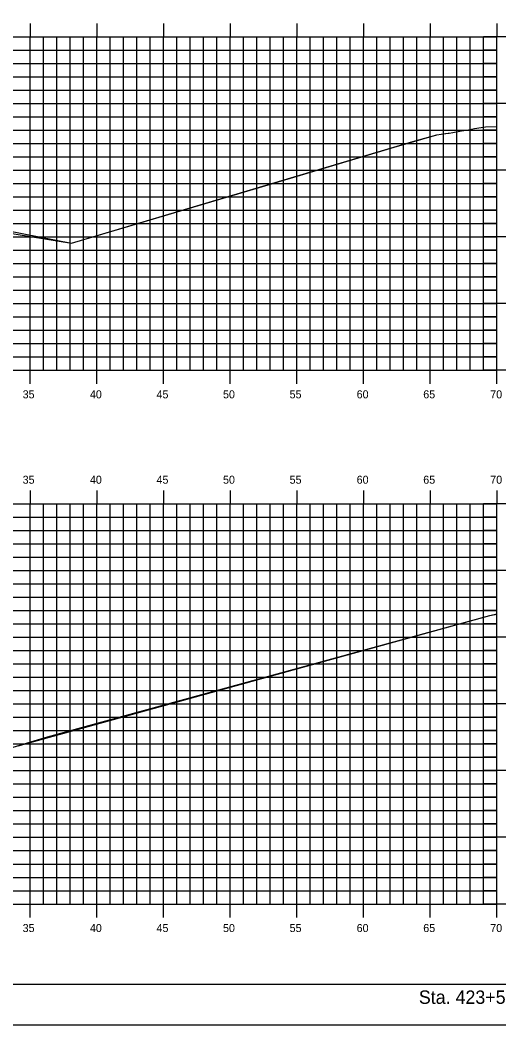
# Model space of a CAD drawing. Extents: x 1168600 to 1177589, y 610178 to 611246.
# Drawn here: x 1174776.1 to 1174812, y 610900.5 to 610975.8 of the extents above; entities that cross this region are included whole.
import ezdxf

# ---------------------------------------------------------------- set-up
doc = ezdxf.new("R2010")
doc.units = 0
for name, color, linetype in [('_Construction', 7, 'Continuous'), ('_Station Equation', 7, 'Continuous'), ('H_V ANNOTATION', 7, 'Continuous'), ('MAJOR', 7, 'Continuous'), ('MINOR', 7, 'Continuous')]:
    doc.layers.add(name, color=color, linetype=linetype)

msp = doc.modelspace()

# ---------------------------------------------------------------- linework, layer by layer
at = {"layer": '_Construction'}
msp.add_line((1174666.88, 610903.596), (1174826.88, 610903.596), dxfattribs=at)
msp.add_lwpolyline([(1174658.787, 610900.537), (1174828.787, 610900.537), (1174828.787, 611010.537), (1174658.787, 611010.537)], close=True, dxfattribs=at)
at = {"layer": '_Station Equation'}
for points in [[(1174689.898, 610959.391), (1174709.446, 610961.528), (1174724.212, 610962.049), (1174731.329, 610961.925), (1174745.178, 610961.326), (1174759.498, 610960.992), (1174772.679, 610960.549), (1174779.992, 610959.119), (1174805.578, 610966.736), (1174807.375, 610967.247), (1174808.025, 610967.336), (1174808.055, 610967.343), (1174808.217, 610967.367), (1174808.29, 610967.378), (1174808.572, 610967.421), (1174808.705, 610967.447), (1174808.852, 610967.478), (1174808.966, 610967.503), (1174809.234, 610967.549), (1174809.742, 610967.631), (1174810.19, 610967.708), (1174811.024, 610967.837), (1174811.88, 610967.868)], [(1174770.741, 610960.613), (1174779.992, 610959.119), (1174794.988, 610963.583), (1174804.189, 610966.323), (1174807.375, 610967.247), (1174808.025, 610967.336), (1174808.055, 610967.343), (1174808.216, 610967.367), (1174808.29, 610967.378), (1174808.572, 610967.421), (1174808.705, 610967.447), (1174808.852, 610967.478), (1174808.966, 610967.503), (1174809.234, 610967.549), (1174809.741, 610967.631), (1174810.19, 610967.708), (1174811.024, 610967.837), (1174811.88, 610967.868)], [(1174671.88, 610929.002), (1174688.235, 610920.975), (1174706.06, 610922.982), (1174712.304, 610920.417), (1174729.011, 610920.776), (1174736.819, 610920.456), (1174737.986, 610920.431), (1174765.818, 610919.558), (1174768.117, 610919.114), (1174778.192, 610922.119), (1174811.346, 610931.232), (1174811.88, 610931.325)], [(1174775.989, 610921.461), (1174811.346, 610931.232), (1174811.88, 610931.334)]]:
    msp.add_lwpolyline(points, dxfattribs=at)
at = {"layer": 'MAJOR'}
for p, q in [((1174776.88, 610975.598), (1174776.88, 610974.596)), ((1174781.88, 610975.598), (1174781.88, 610974.596)), ((1174786.88, 610975.598), (1174786.88, 610974.596)), ((1174791.88, 610975.598), (1174791.88, 610974.596)), ((1174796.88, 610975.598), (1174796.88, 610974.596)), ((1174801.88, 610975.598), (1174801.88, 610974.596)), ((1174806.88, 610975.598), (1174806.88, 610974.596)), ((1174811.88, 610975.598), (1174811.88, 610974.596)), ((1174671.88, 610974.596), (1174811.88, 610974.596)), ((1174671.88, 610974.596), (1174811.88, 610974.596)), ((1174776.88, 610949.596), (1174776.88, 610974.596)), ((1174781.88, 610949.596), (1174781.88, 610974.596)), ((1174786.88, 610949.596), (1174786.88, 610974.596)), ((1174791.88, 610949.596), (1174791.88, 610974.596)), ((1174796.88, 610949.596), (1174796.88, 610974.596)), ((1174801.88, 610949.596), (1174801.88, 610974.596)), ((1174806.88, 610949.596), (1174806.88, 610974.596)), ((1174812.882, 610974.596), (1174810.878, 610974.596)), ((1174811.88, 610949.596), (1174811.88, 610974.596)), ((1174811.88, 610949.596), (1174811.88, 610974.596)), ((1174671.88, 610969.596), (1174811.88, 610969.596)), ((1174812.882, 610969.596), (1174810.878, 610969.596)), ((1174671.88, 610964.596), (1174811.88, 610964.596)), ((1174812.882, 610964.596), (1174810.878, 610964.596)), ((1174671.88, 610959.596), (1174811.88, 610959.596)), ((1174812.882, 610959.596), (1174810.878, 610959.596)), ((1174671.88, 610954.596), (1174811.88, 610954.596)), ((1174812.882, 610954.596), (1174810.878, 610954.596)), ((1174671.88, 610949.596), (1174811.88, 610949.596)), ((1174671.88, 610949.596), (1174811.88, 610949.596)), ((1174776.88, 610948.594), (1174776.88, 610949.596)), ((1174781.88, 610948.594), (1174781.88, 610949.596)), ((1174786.88, 610948.594), (1174786.88, 610949.596)), ((1174791.88, 610948.594), (1174791.88, 610949.596)), ((1174796.88, 610948.594), (1174796.88, 610949.596)), ((1174801.88, 610948.594), (1174801.88, 610949.596)), ((1174806.88, 610948.594), (1174806.88, 610949.596)), ((1174812.882, 610949.596), (1174810.878, 610949.596)), ((1174811.88, 610948.594), (1174811.88, 610949.596)), ((1174776.88, 610940.598), (1174776.88, 610939.596)), ((1174781.88, 610940.598), (1174781.88, 610939.596)), ((1174786.88, 610940.598), (1174786.88, 610939.596)), ((1174791.88, 610940.598), (1174791.88, 610939.596)), ((1174796.88, 610940.598), (1174796.88, 610939.596)), ((1174801.88, 610940.598), (1174801.88, 610939.596)), ((1174806.88, 610940.598), (1174806.88, 610939.596)), ((1174811.88, 610940.598), (1174811.88, 610939.596)), ((1174671.88, 610939.596), (1174811.88, 610939.596)), ((1174671.88, 610939.596), (1174811.88, 610939.596)), ((1174776.88, 610909.596), (1174776.88, 610939.596)), ((1174781.88, 610909.596), (1174781.88, 610939.596)), ((1174786.88, 610909.596), (1174786.88, 610939.596)), ((1174791.88, 610909.596), (1174791.88, 610939.596)), ((1174796.88, 610909.596), (1174796.88, 610939.596)), ((1174801.88, 610909.596), (1174801.88, 610939.596)), ((1174806.88, 610909.596), (1174806.88, 610939.596)), ((1174812.882, 610939.596), (1174810.878, 610939.596)), ((1174811.88, 610909.596), (1174811.88, 610939.596)), ((1174811.88, 610909.596), (1174811.88, 610939.596)), ((1174671.88, 610934.596), (1174811.88, 610934.596)), ((1174812.882, 610934.596), (1174810.878, 610934.596)), ((1174671.88, 610929.596), (1174811.88, 610929.596)), ((1174812.882, 610929.596), (1174810.878, 610929.596)), ((1174671.88, 610924.596), (1174811.88, 610924.596)), ((1174812.882, 610924.596), (1174810.878, 610924.596)), ((1174671.88, 610919.596), (1174811.88, 610919.596)), ((1174812.882, 610919.596), (1174810.878, 610919.596)), ((1174671.88, 610914.596), (1174811.88, 610914.596)), ((1174812.882, 610914.596), (1174810.878, 610914.596)), ((1174671.88, 610909.596), (1174811.88, 610909.596)), ((1174671.88, 610909.596), (1174811.88, 610909.596)), ((1174776.88, 610908.594), (1174776.88, 610909.596)), ((1174781.88, 610908.594), (1174781.88, 610909.596)), ((1174786.88, 610908.594), (1174786.88, 610909.596)), ((1174791.88, 610908.594), (1174791.88, 610909.596)), ((1174796.88, 610908.594), (1174796.88, 610909.596)), ((1174801.88, 610908.594), (1174801.88, 610909.596)), ((1174806.88, 610908.594), (1174806.88, 610909.596)), ((1174812.882, 610909.596), (1174810.878, 610909.596)), ((1174811.88, 610908.594), (1174811.88, 610909.596))]:
    msp.add_line(p, q, dxfattribs=at)
at = {"layer": 'MINOR'}
for p, q in [((1174777.88, 610949.596), (1174777.88, 610974.596)), ((1174778.88, 610949.596), (1174778.88, 610974.596)), ((1174779.88, 610949.596), (1174779.88, 610974.596)), ((1174780.88, 610949.596), (1174780.88, 610974.596)), ((1174782.88, 610949.596), (1174782.88, 610974.596)), ((1174783.88, 610949.596), (1174783.88, 610974.596)), ((1174784.88, 610949.596), (1174784.88, 610974.596)), ((1174785.88, 610949.596), (1174785.88, 610974.596)), ((1174787.88, 610949.596), (1174787.88, 610974.596)), ((1174788.88, 610949.596), (1174788.88, 610974.596)), ((1174789.88, 610949.596), (1174789.88, 610974.596)), ((1174790.88, 610949.596), (1174790.88, 610974.596)), ((1174792.88, 610949.596), (1174792.88, 610974.596)), ((1174793.88, 610949.596), (1174793.88, 610974.596)), ((1174794.88, 610949.596), (1174794.88, 610974.596)), ((1174795.88, 610949.596), (1174795.88, 610974.596)), ((1174797.88, 610949.596), (1174797.88, 610974.596)), ((1174798.88, 610949.596), (1174798.88, 610974.596)), ((1174799.88, 610949.596), (1174799.88, 610974.596)), ((1174800.88, 610949.596), (1174800.88, 610974.596)), ((1174802.88, 610949.596), (1174802.88, 610974.596)), ((1174803.88, 610949.596), (1174803.88, 610974.596)), ((1174804.88, 610949.596), (1174804.88, 610974.596)), ((1174805.88, 610949.596), (1174805.88, 610974.596)), ((1174807.88, 610949.596), (1174807.88, 610974.596)), ((1174808.88, 610949.596), (1174808.88, 610974.596)), ((1174809.88, 610949.596), (1174809.88, 610974.596)), ((1174810.88, 610949.596), (1174810.88, 610974.596)), ((1174671.88, 610973.596), (1174811.88, 610973.596)), ((1174811.88, 610973.596), (1174810.878, 610973.596)), ((1174671.88, 610972.596), (1174811.88, 610972.596)), ((1174811.88, 610972.596), (1174810.878, 610972.596)), ((1174671.88, 610971.596), (1174811.88, 610971.596)), ((1174811.88, 610971.596), (1174810.878, 610971.596)), ((1174671.88, 610970.596), (1174811.88, 610970.596)), ((1174811.88, 610970.596), (1174810.878, 610970.596)), ((1174671.88, 610968.596), (1174811.88, 610968.596)), ((1174811.88, 610968.596), (1174810.878, 610968.596)), ((1174671.88, 610967.596), (1174811.88, 610967.596)), ((1174811.88, 610967.596), (1174810.878, 610967.596)), ((1174671.88, 610966.596), (1174811.88, 610966.596)), ((1174811.88, 610966.596), (1174810.878, 610966.596)), ((1174671.88, 610965.596), (1174811.88, 610965.596)), ((1174811.88, 610965.596), (1174810.878, 610965.596)), ((1174671.88, 610963.596), (1174811.88, 610963.596)), ((1174811.88, 610963.596), (1174810.878, 610963.596)), ((1174671.88, 610962.596), (1174811.88, 610962.596)), ((1174811.88, 610962.596), (1174810.878, 610962.596)), ((1174671.88, 610961.596), (1174811.88, 610961.596)), ((1174811.88, 610961.596), (1174810.878, 610961.596)), ((1174671.88, 610960.596), (1174811.88, 610960.596)), ((1174811.88, 610960.596), (1174810.878, 610960.596)), ((1174671.88, 610958.596), (1174811.88, 610958.596)), ((1174811.88, 610958.596), (1174810.878, 610958.596)), ((1174671.88, 610957.596), (1174811.88, 610957.596)), ((1174811.88, 610957.596), (1174810.878, 610957.596)), ((1174671.88, 610956.596), (1174811.88, 610956.596)), ((1174811.88, 610956.596), (1174810.878, 610956.596)), ((1174671.88, 610955.596), (1174811.88, 610955.596)), ((1174811.88, 610955.596), (1174810.878, 610955.596)), ((1174671.88, 610953.596), (1174811.88, 610953.596)), ((1174811.88, 610953.596), (1174810.878, 610953.596)), ((1174671.88, 610952.596), (1174811.88, 610952.596)), ((1174811.88, 610952.596), (1174810.878, 610952.596)), ((1174671.88, 610951.596), (1174811.88, 610951.596)), ((1174811.88, 610951.596), (1174810.878, 610951.596)), ((1174671.88, 610950.596), (1174811.88, 610950.596)), ((1174811.88, 610950.596), (1174810.878, 610950.596)), ((1174777.88, 610909.596), (1174777.88, 610939.596)), ((1174778.88, 610909.596), (1174778.88, 610939.596)), ((1174779.88, 610909.596), (1174779.88, 610939.596)), ((1174780.88, 610909.596), (1174780.88, 610939.596)), ((1174782.88, 610909.596), (1174782.88, 610939.596)), ((1174783.88, 610909.596), (1174783.88, 610939.596)), ((1174784.88, 610909.596), (1174784.88, 610939.596)), ((1174785.88, 610909.596), (1174785.88, 610939.596)), ((1174787.88, 610909.596), (1174787.88, 610939.596)), ((1174788.88, 610909.596), (1174788.88, 610939.596)), ((1174789.88, 610909.596), (1174789.88, 610939.596)), ((1174790.88, 610909.596), (1174790.88, 610939.596)), ((1174792.88, 610909.596), (1174792.88, 610939.596)), ((1174793.88, 610909.596), (1174793.88, 610939.596)), ((1174794.88, 610909.596), (1174794.88, 610939.596)), ((1174795.88, 610909.596), (1174795.88, 610939.596)), ((1174797.88, 610909.596), (1174797.88, 610939.596)), ((1174798.88, 610909.596), (1174798.88, 610939.596)), ((1174799.88, 610909.596), (1174799.88, 610939.596)), ((1174800.88, 610909.596), (1174800.88, 610939.596)), ((1174802.88, 610909.596), (1174802.88, 610939.596)), ((1174803.88, 610909.596), (1174803.88, 610939.596)), ((1174804.88, 610909.596), (1174804.88, 610939.596)), ((1174805.88, 610909.596), (1174805.88, 610939.596)), ((1174807.88, 610909.596), (1174807.88, 610939.596)), ((1174808.88, 610909.596), (1174808.88, 610939.596)), ((1174809.88, 610909.596), (1174809.88, 610939.596)), ((1174810.88, 610909.596), (1174810.88, 610939.596)), ((1174671.88, 610938.596), (1174811.88, 610938.596)), ((1174811.88, 610938.596), (1174810.878, 610938.596)), ((1174671.88, 610937.596), (1174811.88, 610937.596)), ((1174811.88, 610937.596), (1174810.878, 610937.596)), ((1174671.88, 610936.596), (1174811.88, 610936.596)), ((1174811.88, 610936.596), (1174810.878, 610936.596)), ((1174671.88, 610935.596), (1174811.88, 610935.596)), ((1174811.88, 610935.596), (1174810.878, 610935.596)), ((1174671.88, 610933.596), (1174811.88, 610933.596)), ((1174811.88, 610933.596), (1174810.878, 610933.596)), ((1174671.88, 610932.596), (1174811.88, 610932.596)), ((1174811.88, 610932.596), (1174810.878, 610932.596)), ((1174671.88, 610931.596), (1174811.88, 610931.596)), ((1174811.88, 610931.596), (1174810.878, 610931.596)), ((1174671.88, 610930.596), (1174811.88, 610930.596)), ((1174811.88, 610930.596), (1174810.878, 610930.596)), ((1174671.88, 610928.596), (1174811.88, 610928.596)), ((1174811.88, 610928.596), (1174810.878, 610928.596)), ((1174671.88, 610927.596), (1174811.88, 610927.596)), ((1174811.88, 610927.596), (1174810.878, 610927.596)), ((1174671.88, 610926.596), (1174811.88, 610926.596)), ((1174811.88, 610926.596), (1174810.878, 610926.596)), ((1174671.88, 610925.596), (1174811.88, 610925.596)), ((1174811.88, 610925.596), (1174810.878, 610925.596)), ((1174671.88, 610923.596), (1174811.88, 610923.596)), ((1174811.88, 610923.596), (1174810.878, 610923.596)), ((1174671.88, 610922.596), (1174811.88, 610922.596)), ((1174811.88, 610922.596), (1174810.878, 610922.596)), ((1174671.88, 610921.596), (1174811.88, 610921.596)), ((1174811.88, 610921.596), (1174810.878, 610921.596)), ((1174671.88, 610920.596), (1174811.88, 610920.596)), ((1174811.88, 610920.596), (1174810.878, 610920.596)), ((1174671.88, 610918.596), (1174811.88, 610918.596)), ((1174811.88, 610918.596), (1174810.878, 610918.596)), ((1174671.88, 610917.596), (1174811.88, 610917.596)), ((1174811.88, 610917.596), (1174810.878, 610917.596)), ((1174671.88, 610916.596), (1174811.88, 610916.596)), ((1174811.88, 610916.596), (1174810.878, 610916.596)), ((1174671.88, 610915.596), (1174811.88, 610915.596)), ((1174811.88, 610915.596), (1174810.878, 610915.596)), ((1174671.88, 610913.596), (1174811.88, 610913.596)), ((1174811.88, 610913.596), (1174810.878, 610913.596)), ((1174671.88, 610912.596), (1174811.88, 610912.596)), ((1174811.88, 610912.596), (1174810.878, 610912.596)), ((1174671.88, 610911.596), (1174811.88, 610911.596)), ((1174811.88, 610911.596), (1174810.878, 610911.596)), ((1174671.88, 610910.596), (1174811.88, 610910.596)), ((1174811.88, 610910.596), (1174810.878, 610910.596))]:
    msp.add_line(p, q, dxfattribs=at)

# ---------------------------------------------------------------- texts
at = {"layer": 'H_V ANNOTATION'}
for s, height, p in [('35', 0.6, (1174776.321, 610947.496)), ('40', 0.6, (1174781.366, 610947.496)), ('45', 0.6, (1174786.358, 610947.496)), ('50', 0.6, (1174791.345, 610947.496)), ('55', 0.6, (1174796.337, 610947.496)), ('60', 0.6, (1174801.366, 610947.496)), ('65', 0.6, (1174806.358, 610947.496)), ('70', 0.6, (1174811.382, 610947.496)), ('35', 0.6, (1174776.321, 610941.096)), ('40', 0.6, (1174781.366, 610941.096)), ('45', 0.6, (1174786.358, 610941.096)), ('50', 0.6, (1174791.345, 610941.096)), ('55', 0.6, (1174796.337, 610941.096)), ('60', 0.6, (1174801.366, 610941.096)), ('65', 0.6, (1174806.358, 610941.096)), ('70', 0.6, (1174811.382, 610941.096)), ('35', 0.6, (1174776.321, 610907.496)), ('40', 0.6, (1174781.366, 610907.496)), ('45', 0.6, (1174786.358, 610907.496)), ('50', 0.6, (1174791.345, 610907.496)), ('55', 0.6, (1174796.337, 610907.496)), ('60', 0.6, (1174801.366, 610907.496)), ('65', 0.6, (1174806.358, 610907.496)), ('70', 0.6, (1174811.382, 610907.496)), ('Sta. 423+50.00 to Sta. 424+00.00', 1.0002, (1174806.026, 610902.116))]:
    msp.add_text(s, height=height, dxfattribs=at).set_placement(p)

doc.saveas('drawing.dxf')
